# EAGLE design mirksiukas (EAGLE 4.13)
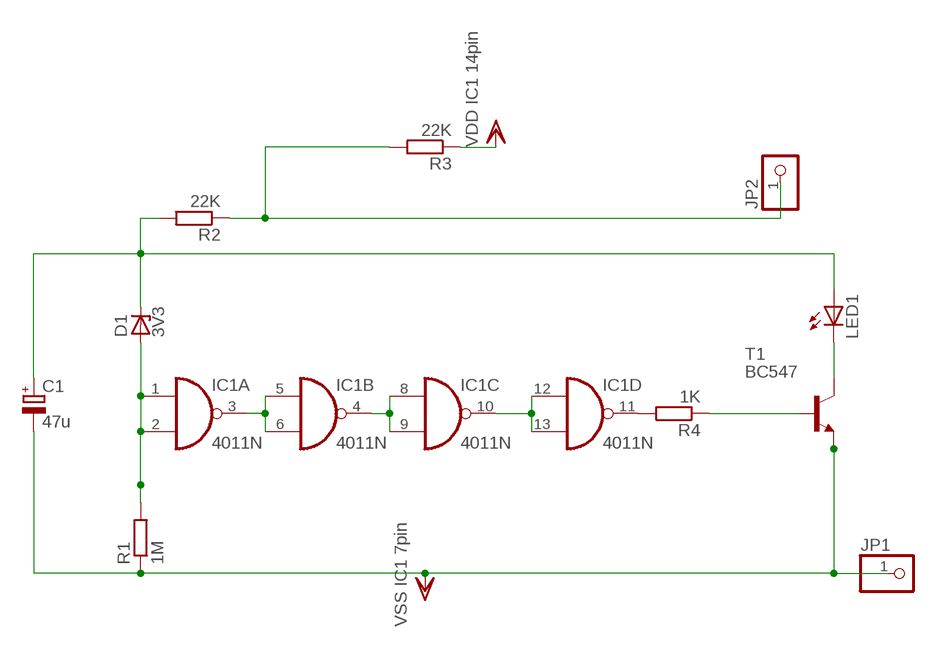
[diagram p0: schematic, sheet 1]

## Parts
C1  47u  CPOL-EUE2-5  [E2-5]
D1  3V3  ZENER-DIODEDO34-7  [DO34Z7]
IC1  4011N  [DIL14]
JP1  PINHD-1X1  [1X01]
JP2  PINHD-1X1  [1X01]
LED1  LED5MM  [LED5MM]
R1  1M  R-EU_0207/10  [0207/10]
R2  22K  R-EU_0207/10  [0207/10]
R3  22K  R-EU_0207/10  [0207/10]
R4  1K  R-EU_0207/10  [0207/10]
T1  BC547  [TO92]

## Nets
N$1: IC1.3(A:O) IC1.5(B:I0) IC1.6(B:I1)
N$2: IC1.4(B:O) IC1.8(C:I0) IC1.9(C:I1)
N$3: IC1.10(C:O) IC1.12(D:I0) IC1.13(D:I1)
N$4: IC1.11(D:O) R4.2
N$6: LED1.K(C) T1.3(C)
N$7: D1.A IC1.1(A:I0) IC1.2(A:I1) R1.2
N$8: JP2.1 R2.1 R3.2
N$9: R4.1 T1.2(B)
N$10: C1.+ D1.C LED1.A R2.2
VDD: R3.1 ; supply symbol labelled VDD IC1 14pin
VSS: C1.- JP1.1 R1.1 T1.1(E) ; supply symbol labelled VSS IC1 7pin

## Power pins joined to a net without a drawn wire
VDD: IC1.14(P:VDD)
VSS: IC1.7(P:VSS)

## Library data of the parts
C1 = rcl:CPOL-EU: POLARIZED CAPACITOR, European symbol
D1 = diode:ZENER-DIODE: Z-Diode
IC1 = 40xx:4011: Quad 2-input NAND
JP1 JP2 = pinhead:PINHD-1X1: PIN HEADER
LED1 = led:LED: LED
R1-R4 = rcl:R-EU_: RESISTOR, European symbol
T1 = transistor:BC547: NPN TRANSISTOR

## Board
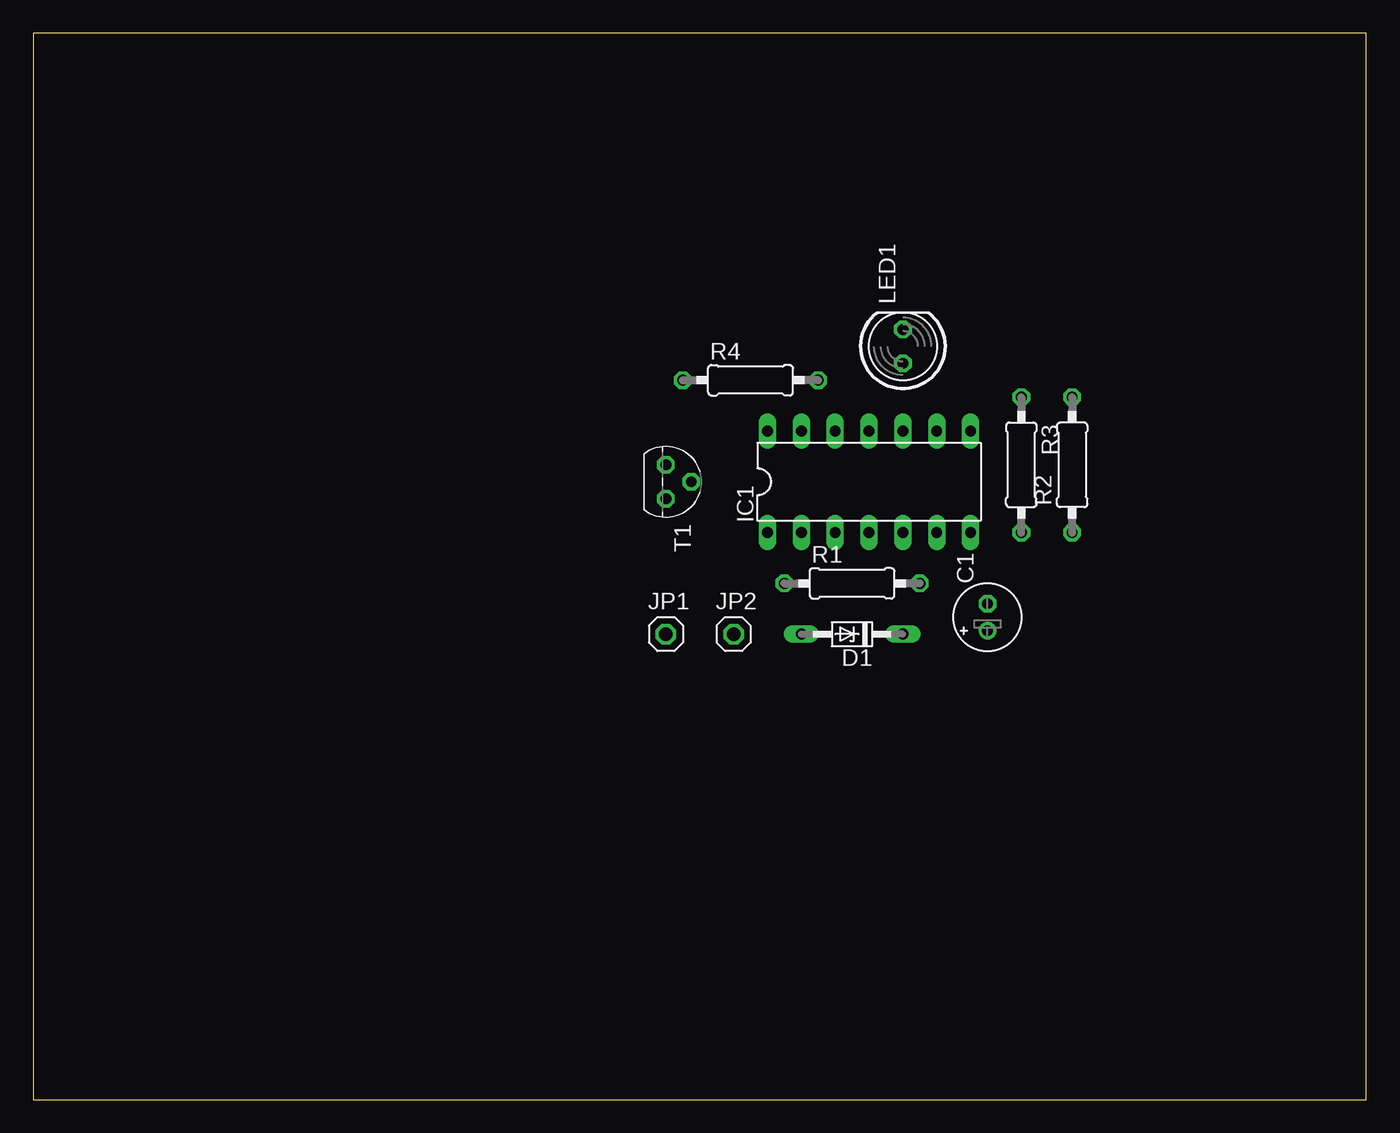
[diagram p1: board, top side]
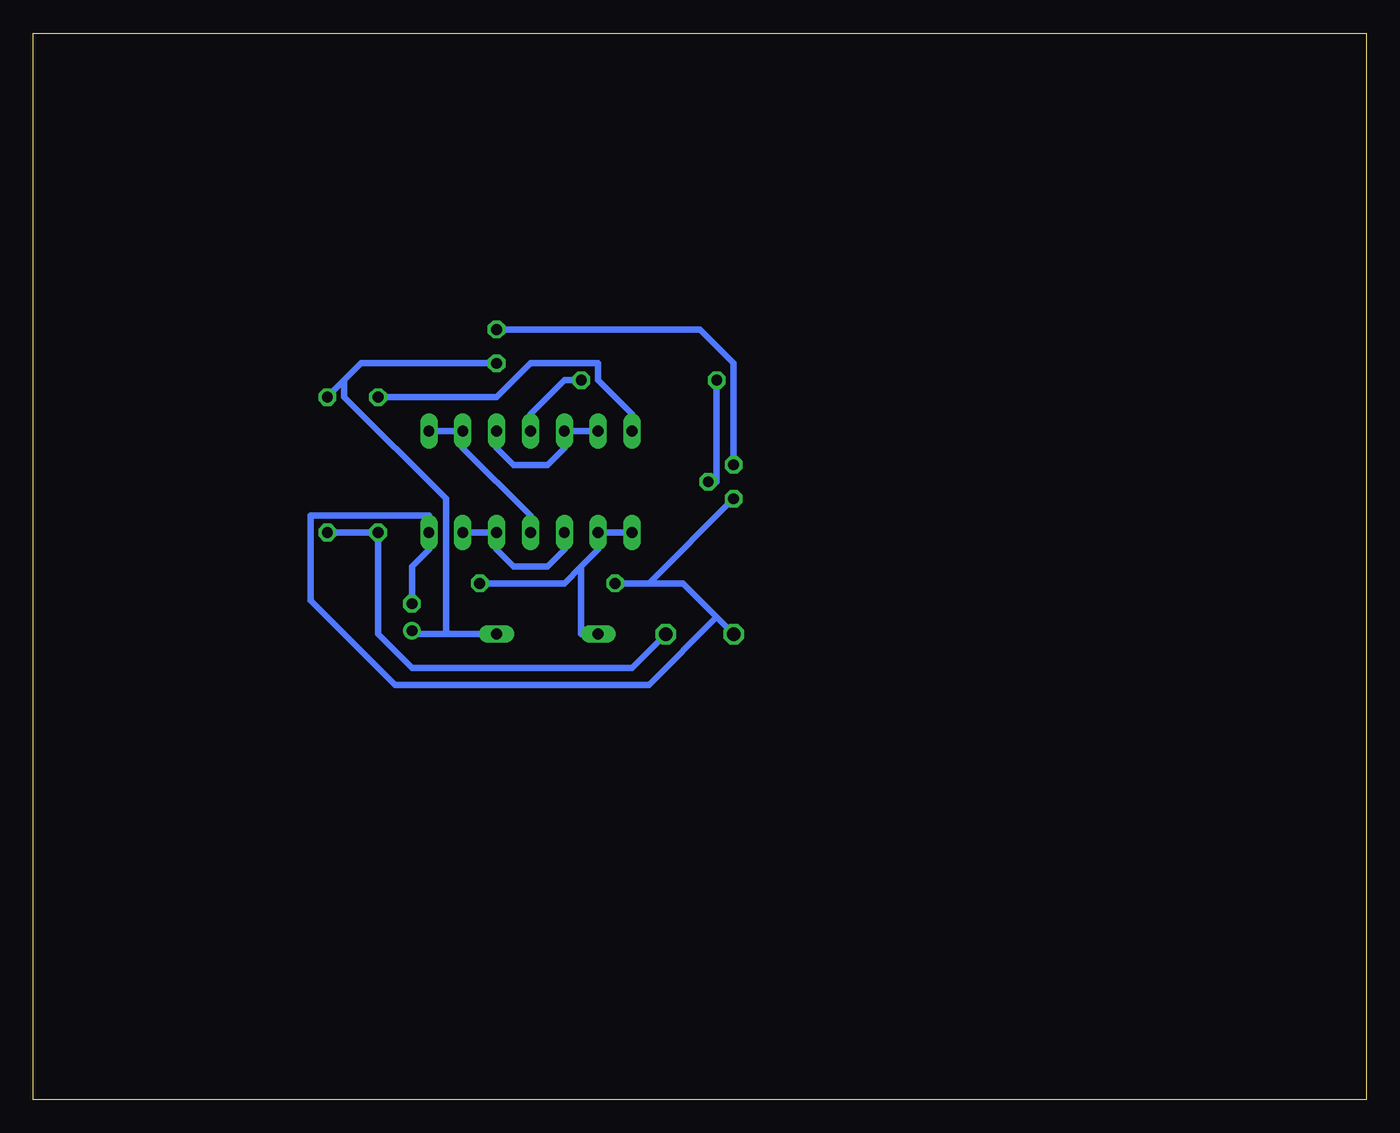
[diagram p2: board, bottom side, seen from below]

Size 100 x 80 mm. Coordinates in mm from the lower left corner, seen from the top.
Outline: 0,0 100,0 100,80 0,80 0,0
Copper layers (1*16): Top 0.035mm / dielectric 1.5mm / Bottom 0.035mm
Design rules "05": minimum track width 0.5mm, minimum drill 24mil, track to track 0.5mm, track to pad 8mil, pad to pad 8mil, via to via 8mil, smd to smd 8mil, copper to edge 40mil, drill to drill 8mil, minimum pad ring 10mil, minimum via ring 8mil, stop-mask expansion 4mil, vias tented up to drill 0mil, thermal gap 10mil

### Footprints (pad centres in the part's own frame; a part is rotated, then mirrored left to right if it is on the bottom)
E2-5 = drill 0.813 pad 1.27 round: + -1.016,0 | drill 0.813 pad 1.27 octagon: - 1.016,0
DO34Z7 = drill 0.813 long: A 3.81,0; C -3.81,0
DIL14 = drill 0.813 long: 1 -7.62,-3.81; 2 -5.08,-3.81; 3 -2.54,-3.81; 4 0,-3.81; 5 2.54,-3.81; 6 5.08,-3.81; 7 7.62,-3.81; 8 7.62,3.81; 9 5.08,3.81; 10 2.54,3.81; 11 0,3.81; 12 -2.54,3.81; 13 -5.08,3.81; 14 -7.62,3.81
1X01 = drill 1.016 octagon: 1 0,0
LED5MM = drill 0.813 octagon: A -1.27,0; K 1.27,0
0207/10 = drill 0.813 octagon: 1 -5.08,0; 2 5.08,0
TO92 = drill 0.813 octagon: 1 1.27,0; 2 0,1.905; 3 -1.27,0

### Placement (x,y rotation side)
C1  71.59,36.19 90 top
D1  61.43,34.92 180 top
IC1  62.7,46.35 0 top
JP1  47.46,34.92 0 top
JP2  52.54,34.92 0 top
LED1  65.24,56.51 90 top
R1  61.43,38.73 0 top
R2  77.94,47.62 90 top
R3  74.13,47.62 270 top
R4  53.81,53.97 0 top
T1  47.46,46.35 270 top

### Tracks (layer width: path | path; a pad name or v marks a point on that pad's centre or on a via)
N$1
  Bottom 0.5: IC1.3 60.16,41.27 61.43,40 63.97,40 65.24,41.27 IC1.5 IC1.6
N$2
  Bottom 0.5: IC1.4 62.7,43.81 67.78,48.89 IC1.9 IC1.8
N$3
  Bottom 0.5: IC1.13 IC1.12 60.16,48.89 61.43,47.62 63.97,47.62 65.24,48.89 IC1.10
N$4
  Bottom 0.5: R4.2 60.16,53.97 62.7,51.43 IC1.11
N$6
  Bottom 0.5: T1.3 47.46,55.24 50,57.78 LED1.K
N$7
  Bottom 0.5: R1.2 60.16,38.73 58.89,40 | 58.89,40 57.62,41.27 IC1.2 IC1.1 | 58.89,40 58.89,34.92 D1.A
N$8
  Bottom 0.5: R2.1 R3.2 74.13,34.92 71.59,32.38 55.08,32.38 JP2.1
N$9
  Bottom 0.5: R4.1 48.73,46.35 T1.2
N$10
  Bottom 0.5: 69.05,34.92 71.59,34.92 C1.+ | 76.67,53.97 75.4,55.24 LED1.A | 76.67,53.97 R2.2 | 69.05,34.92 69.05,45.08 76.67,52.7 76.67,53.97 | D1.C 69.05,34.92
VDD
  Bottom 0.5: R3.1 65.24,52.7 62.7,55.24 57.62,55.24 57.62,53.97 55.08,51.43 IC1.14
VSS
  Bottom 0.5: C1.- 71.59,40 70.32,41.27 IC1.7 70.32,43.81 79.21,43.81 79.21,37.46 72.86,31.11 53.81,31.11 48.73,36.19 | 53.81,38.73 51.27,38.73 48.73,36.19 | 53.81,38.73 R1.1 | JP1.1 48.73,36.19 | 53.81,38.73 T1.1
